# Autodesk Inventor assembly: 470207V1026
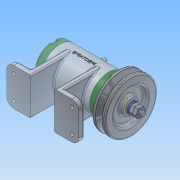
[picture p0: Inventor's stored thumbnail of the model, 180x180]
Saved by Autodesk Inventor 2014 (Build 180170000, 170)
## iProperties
Created: 2017-02
Part Number: 470207V1026
Document SubType Name: Assembly
Designer: NET
Author: NET
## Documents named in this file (16)
- C:\Users\NET\Desktop\470207V1026\470207V1026.iam
- C:\Users\NET\Desktop\470207V1026\470207V1026.ipt
- C:\Users\NET\Desktop\470207V1026\V벨트풀리.ipt
- C:\Users\NET\Desktop\470207V1026\너트 M 8.ipt
- C:\Users\NET\Desktop\470207V1026\니플 M 6 x 0.75.ipt
- C:\Users\NET\Desktop\470207V1026\뒤커버.ipt
- C:\Users\NET\Desktop\470207V1026\베어링 15 x 32 x 9.ipt
- C:\Users\NET\Desktop\470207V1026\볼트 M 6 x 8.ipt
- C:\Users\NET\Desktop\470207V1026\볼트 M4 x 12.ipt
- C:\Users\NET\Desktop\470207V1026\스프링와셔 8.ipt
- C:\Users\NET\Desktop\470207V1026\앞커버.ipt
- C:\Users\NET\Desktop\470207V1026\오일 실 15 25 7.ipt
- C:\Users\NET\Desktop\470207V1026\와셔 6x11.5.ipt
- C:\Users\NET\Desktop\470207V1026\와셔 8x17.ipt
- C:\Users\NET\Desktop\470207V1026\축.ipt
- C:\Users\NET\Desktop\470207V1026\키 3 x 3 x 12.ipt
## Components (12 placed, 4 different names)
1. 470207V1026:1 — 각도:1
2. V벨트풀리:1
3. KS B 2023 6002 - 15 x 32 x 9:1
4. KS B 2023 6002 - 15 x 32 x 9:2
5. ISO 4762 M4 x 12:1
6. ISO 4762 M4 x 12:2
7. ISO 4762 M4 x 12:3
8. ISO 4762 M4 x 12:4
9. ISO 4762 M4 x 12:5
10. ISO 4762 M4 x 12:6
11. ISO 4762 M4 x 12:7
12. ISO 4762 M4 x 12:8
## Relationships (1: Angle 1)
- 각도:1 [Angle]: 470207V1026:1
